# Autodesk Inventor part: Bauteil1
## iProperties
Created: 2005-01
Part Number: Bauteil1
Cost Center: 0 kg
Material: 2.1293 Cu-Cr1Zr
Document SubType Name: Modeling
Designer: Stefan
Manufacturer: Standard
Standards Organization: Custom
SaveDate: 2004-08-11
SaveTime: 16:49
TotalMass: 0 kg
Author: Stefan
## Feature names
1. Extrusion2
